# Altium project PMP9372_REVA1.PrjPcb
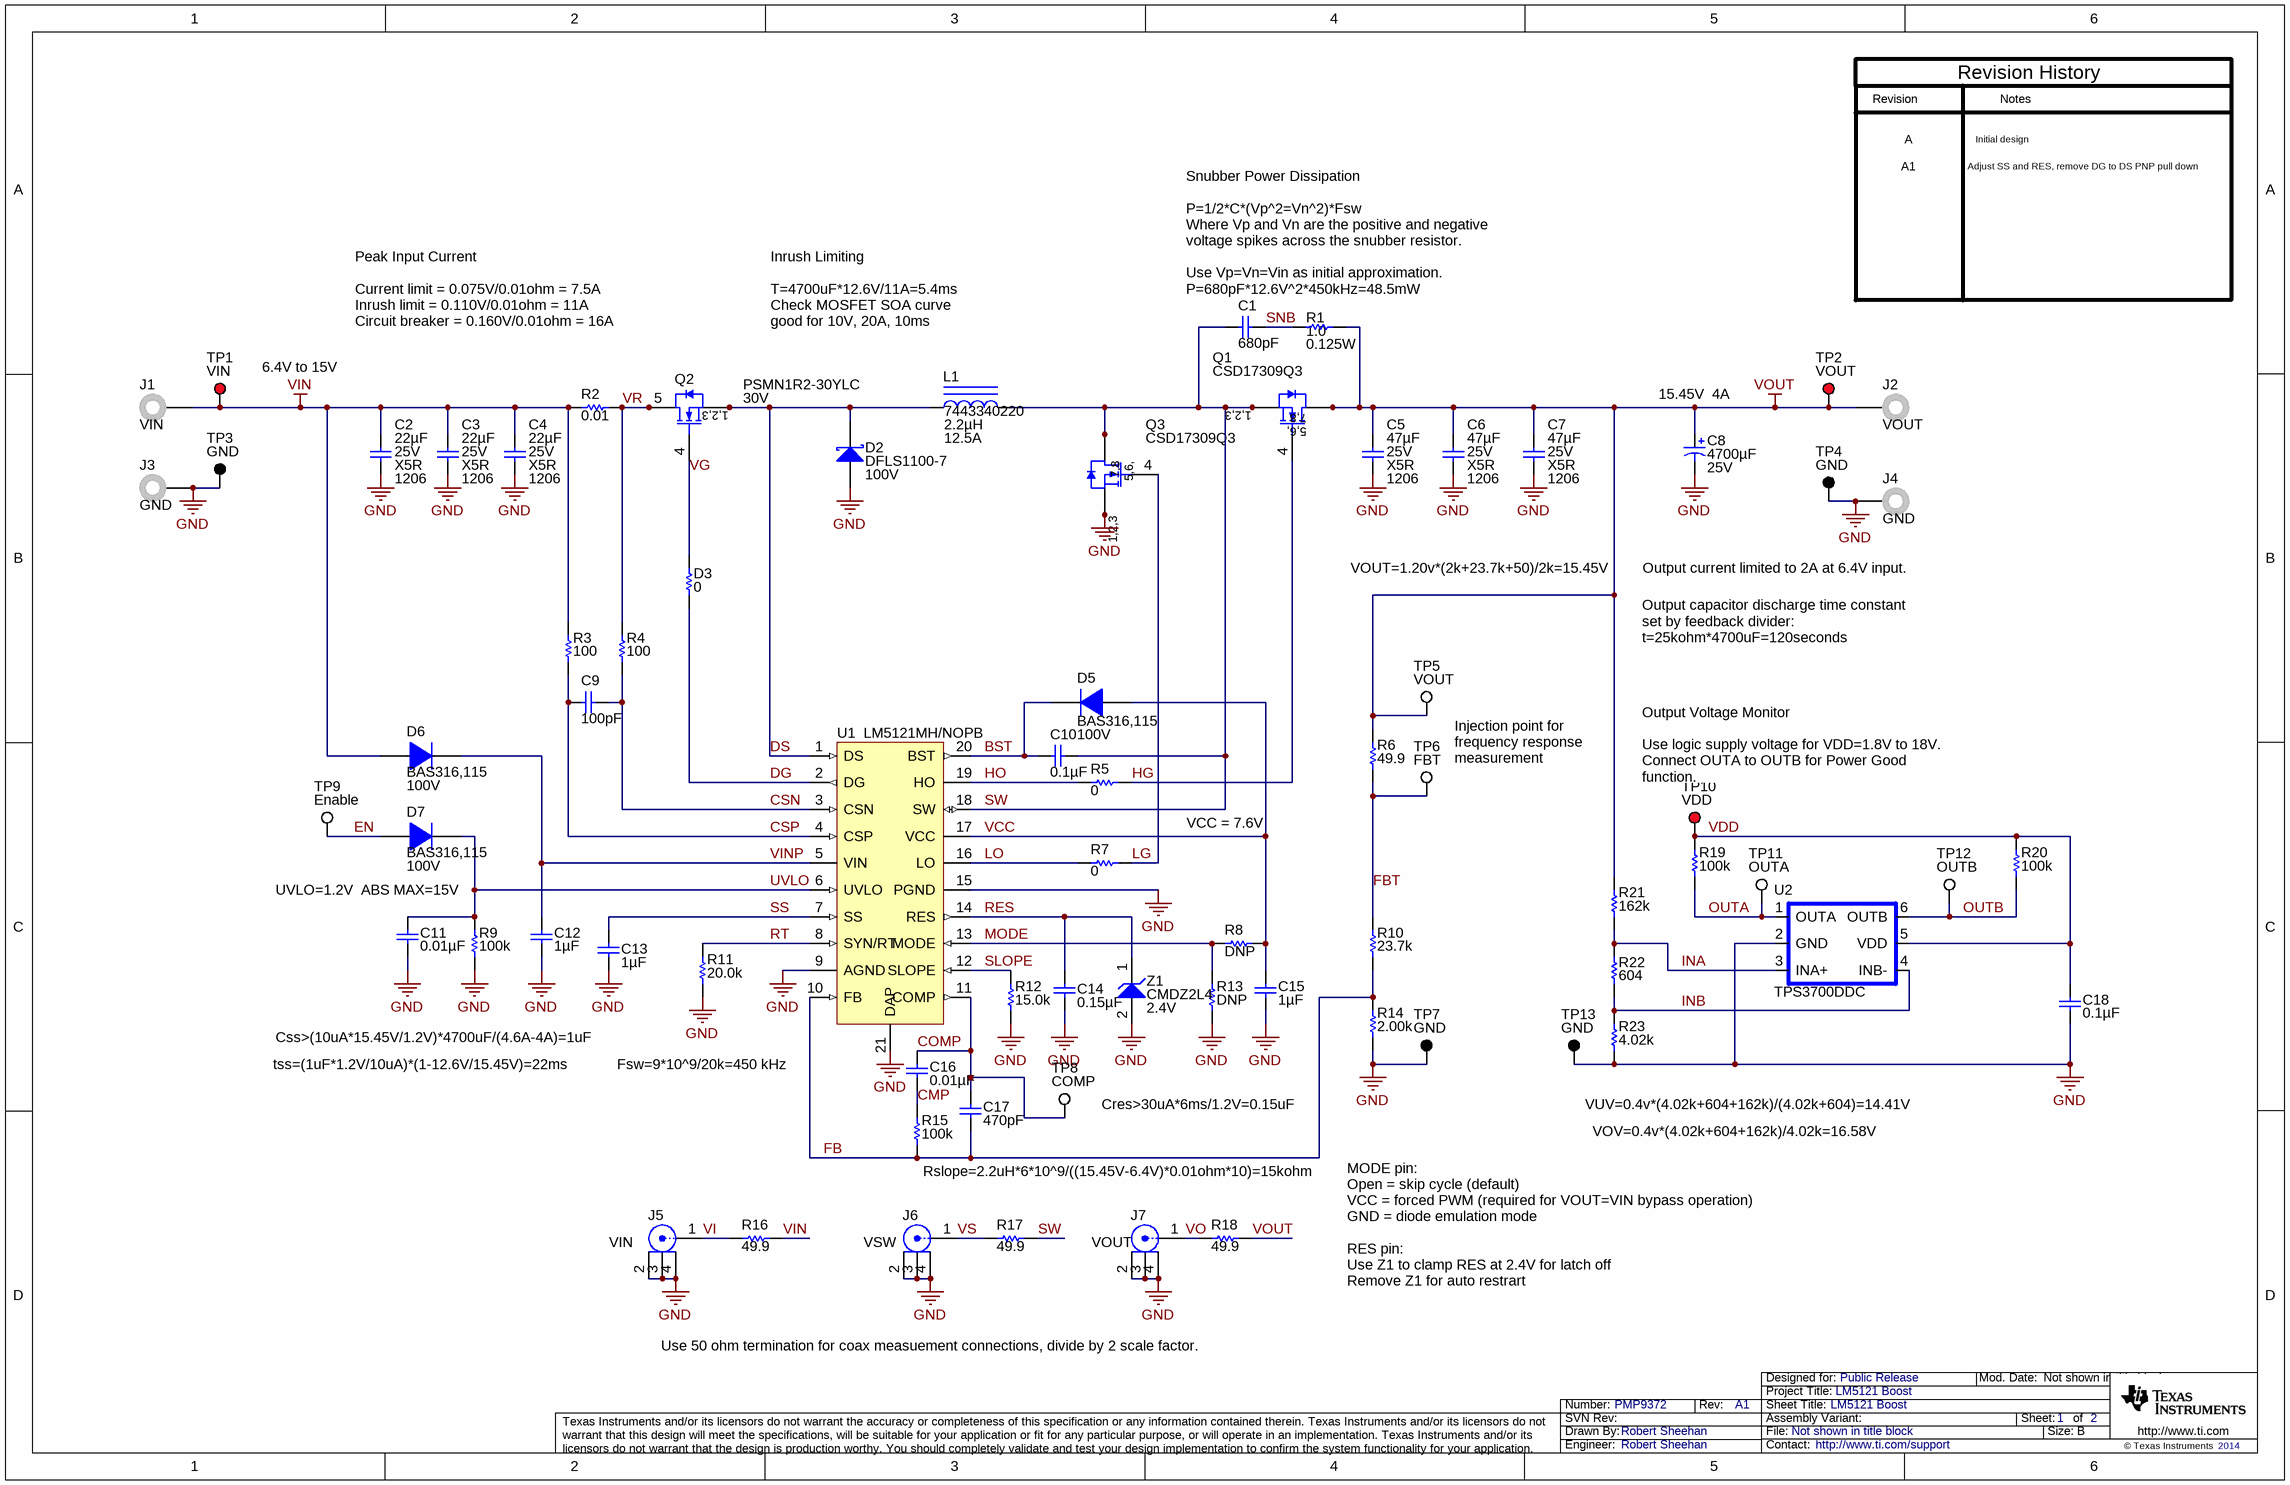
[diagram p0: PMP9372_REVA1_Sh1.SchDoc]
TechSupport: http://www.ti.com/support; SCH_Rev: A1; PRJ_Title: LM5121 Boost; PRJ_Number: PMP9372; PRJ_Engineer: Robert Sheehan; PRJ_Customer: Public Release; PCB_Rev: A; PCB_Layout: Robert Sheehan; CopyrightYear: 2014
2 sheets, 91 parts. Net scope: global (net labels, ports and power ports of the same name join across sheets).
Board file: PMP9372_REVA.PcbDoc
Sheets:
  PMP9372_REVA1_Sh1.SchDoc
  PMP9372_REVA1_Sh2.SchDoc

## Sheet PMP9372_REVA1_Sh1.SchDoc: LM5121 Boost
size 431 x 279 mm; Date: Not shown in title block; ApprovedBy: Not shown in title block; CheckedBy: Not shown in title block; Author: Not shown in title block; CompanyName: Not shown in title block; DrawnBy: Robert Sheehan; Engineer: Not shown in title block; Organization: Not shown in title block; Address1: Not shown in title block; Address2: Not shown in title block; Address3: Not shown in title block; Address4: Not shown in title block; DocumentNumber: 1; Revision: Use project parameter SCH_Rev; SheetNumber: 1; SheetTotal: 2; PageSetup: Record=PageOptions|CenterHorizontal=True|CenterVertical=True|PrintScale=1.00|XCorrection=1.00|YCorrection=1.00|PrintKind=0|BorderSize=5000000|LeftOffset=0|BottomOffset=0|Orientation=2|PaperLength=1000|PaperWidth=1000|Scale=100|PaperSource=15|PrintQuality=600|MediaType=1|DitherType=10|PaperKind=Letter|PrintScaleMode=1

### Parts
C1  ValueDisplayed: 680pF  [0603]  (hidden comment: GRM1885C1H681JA01D)
C2  TempCo: X5R  Value2: 25V  ValueDisplayed: 22µF  [1206]  (hidden comment: GRM31CR61E226KE15L)
C3  TempCo: X5R  Value2: 25V  ValueDisplayed: 22µF  [1206]  (hidden comment: GRM31CR61E226KE15L)
C4  TempCo: X5R  Value2: 25V  ValueDisplayed: 22µF  [1206]  (hidden comment: GRM31CR61E226KE15L)
C5  TempCo: X5R  Value2: 25V  ValueDisplayed: 47µF  [1206]  (hidden comment: C3216X5R1E476M160AC)
C6  TempCo: X5R  Value2: 25V  ValueDisplayed: 47µF  [1206]  (hidden comment: C3216X5R1E476M160AC)
C7  TempCo: X5R  Value2: 25V  ValueDisplayed: 47µF  [1206]  (hidden comment: C3216X5R1E476M160AC)
C8  ValueDisplayed: 4700µF  Value2: 25V  [CAPPR7.5-16X31.5H2]  (hidden comment: UKA1E472MHD)
C9  ValueDisplayed: 100pF  [0402]  (hidden comment: GRM1555C1H101JA01D)
C10  ValueDisplayed: 0.1µF  [0603_HV]  (hidden comment: GRM188R71C104KA01D)
C11  ValueDisplayed: 0.01µF  [0402]  (hidden comment: GRM155R71H103KA88D)
C12  ValueDisplayed: 1µF  [0402]  (hidden comment: C1005X5R1E105K050BC)
C13  ValueDisplayed: 1µF  [0402]  (hidden comment: C1005X5R1E105K050BC)
C14  ValueDisplayed: 0.15µF  [0402]  (hidden comment: GRM155R61A154KE19D)
C15  ValueDisplayed: 1µF  [0603_HV]  (hidden comment: GRM188R61E105KA12D)
C16  ValueDisplayed: 0.01µF  [0402]  (hidden comment: GRM155R71E103KA01D)
C17  ValueDisplayed: 470pF  [0402]  (hidden comment: C1005C0G1H471J)
C18  ValueDisplayed: 0.1µF  [0603_HV]  (hidden comment: GRM188R71C104KA01D)
D2  DFLS1100-7  value 100V  [powerDI123]
D3  value 0  [0402]  (hidden comment: CRCW04020000Z0ED)
D5  BAS316,115  value 100V  [sod-323]
D6  BAS316,115  value 100V  [sod-323]
D7  BAS316,115  value 100V  [sod-323]
J1  VIN  [Keystone575-8]
J2  VOUT  [Keystone575-8]
J3  GND  [Keystone575-8]
J4  GND  [Keystone575-8]
J5  VIN  [A-1JB]
J6  VSW  [A-1JB]
J7  VOUT  [A-1JB]
L1  7443340220  ValueDisplayed: 2.2µH  Value2: 12.5A  [WE-HCC-8X7]
Q1  CSD17309Q3  [TRANS_NexFET_Q3]
Q2  PSMN1R2-30YLC  value 30V  [LFPAK]
Q3  CSD17309Q3  [TRANS_NexFET_Q3]
R1  value 1.0  Value2: 0.125W  [0805_HV]  (hidden comment: CRCW08051R00JNEA)
R2  value 0.01  [2010M]  (hidden comment: CSRN2010FK10L0)
R3  value 100  [0402]  (hidden comment: CRCW0402100RJNED)
R4  value 100  [0402]  (hidden comment: CRCW0402100RJNED)
R5  value 0  [0402]  (hidden comment: CRCW04020000Z0ED)
R6  value 49.9  [0402]  (hidden comment: CRCW040249R9FKED)
R7  value 0  [0402]  (hidden comment: CRCW04020000Z0ED)
R8  value DNP  [0402]  (hidden comment: DNP1)
R9  value 100k  [0402]  (hidden comment: CRCW0402100KJNED)
R10  value 23.7k  [0402]  (hidden comment: CRCW040223K7FKED)
R11  value 20.0k  [0402]  (hidden comment: CRCW040220K0FKED)
R12  value 15.0k  [0402]  (hidden comment: CRCW040215K0FKED)
R13  value DNP  [0402]  (hidden comment: DNP1)
R14  value 2.00k  [0402]  (hidden comment: CRCW04022K00FKED)
R15  value 100k  [0402]  (hidden comment: CRCW0402100KFKED)
R16  value 49.9  [0603]  (hidden comment: CRCW060349R9FKEA)
R17  value 49.9  [0603]  (hidden comment: CRCW060349R9FKEA)
R18  value 49.9  [0603]  (hidden comment: CRCW060349R9FKEA)
R19  value 100k  [0402]  (hidden comment: CRCW0402100KJNED)
R20  value 100k  [0402]  (hidden comment: CRCW0402100KJNED)
R21  value 162k  [0402]  (hidden comment: CRCW0402162KFKED)
R22  value 604  [0402]  (hidden comment: CRCW0402604RFKED)
R23  value 4.02k  [0402]  (hidden comment: CRCW04024K02FKED)
TP1  VIN  [Keystone5010]
TP2  VOUT  [Keystone5010]
TP3  GND  [Keystone5011]
TP4  GND  [Keystone5011]
TP5  VOUT  [Keystone5012]
TP6  FBT  [Keystone5012]
TP7  GND  [Keystone5011]
TP8  COMP  [Keystone5012]
TP9  Enable  [Keystone5012]
TP10  VDD  [Keystone5010]
TP11  OUTA  [Keystone5012]
TP12  OUTB  [Keystone5012]
TP13  GND  [Keystone5011]
U1  LM5121MH/NOPB  [PWP0020A_N]
U2  TPS3700DDC  [SOT23-6]
Z1  CMDZ2L4  value 2.4V  [sod-323]

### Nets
GND: C2.2 C3.2 C4.2 C5.2 C6.2 C7.2 C8.2(-) C11.2 C12.2 C13.2 C14.2 C15.2 C18.1 D2.2(A) J3.1 J4.1 J5.2 J5.3 J5.4 J6.2 J6.3 J6.4 J7.2 J7.3 J7.4 Q3.1(S) Q3.2(S) Q3.3(S) R9.1 R11.1 R12.1 R13.1 R14.1 R23.1 TP3.1 TP4.1 TP7.1 TP13.1 U1.9(AGND) U1.15(PGND) U1.21(DAP) U2.2(GND) Z1.2(A)
VIN: C2.1 C3.1 C4.1 D6.2(A) J1.1 R2.1 R3.2 R16.2 TP1.1
VOUT: C5.1 C6.1 C7.1 C8.1(+) J2.1 Q1.5(D) Q1.6(D) Q1.7(D) Q1.8(D) R1.2 R6.2 R18.2 R21.2 TP2.1 TP5.1
BST: C10.1 D5.1(K) U1.20(BST)
CMP: C16.2 R15.2
COMP: C16.1 C17.2 TP8.1 U1.11(COMP)
CSN: C9.1 R4.1 U1.3(CSN)
CSP: C9.2 R3.1 U1.4(CSP)
DG: D3.2 U1.2(DG)
DS: D2.1(K) L1.1 Q2.1(S) Q2.2(S) Q2.3(S) U1.1(DS)
EN: D7.2(A) TP9.1
FB: C17.1 R10.1 R14.2 R15.1 U1.10(FB)
FBT: R6.1 R10.2 TP6.1
HG: Q1.4(G) R5.2
HO: R5.1 U1.19(HO)
INA: R21.1 R22.2 U2.3(INA+)
INB: R22.1 R23.2 U2.4(INB-)
LG: Q3.4(G) R7.2
LO: R7.1 U1.16(LO)
MODE: R8.2 R13.2 U1.13(MODE)
OUTA: R19.1 TP11.1 U2.1(OUTA)
OUTB: R20.1 TP12.1 U2.6(OUTB)
RES: C14.1 U1.14(RES) Z1.1(K)
RT: R11.2 U1.8(SYN/RT)
SLOPE: R12.2 U1.12(SLOPE)
SNB: C1.1 R1.1
SS: C13.1 U1.7(SS)
SW: C1.2 C10.2 L1.2 Q1.1(S) Q1.2(S) Q1.3(S) Q3.5(D) Q3.6(D) Q3.7(D) Q3.8(D) R17.2 U1.18(SW)
UVLO: C11.1 D7.1(K) R9.2 U1.6(UVLO)
VCC: C15.1 D5.2(A) R8.1 U1.17(VCC)
VDD: C18.2 R19.2 R20.2 TP10.1 U2.5(VDD)
VG: D3.1 Q2.4(G)
VI: J5.1 R16.1
VINP: C12.1 D6.1(K) U1.5(VIN)
VO: J7.1 R18.1
VR: Q2.5(D) Q2.6(D) R2.2 R4.2
VS: J6.1 R17.1

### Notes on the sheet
- Revision
- Notes
- Revision History
- A
- A1
- Initial design
- Adjust SS and RES, remove DG to DS PNP pull down
- Snubber Power Dissipation
  P=1/2*C*(Vp^2=Vn^2)*Fsw
  Where Vp and Vn are the positive and negative voltage spikes across the snubber resistor.
  Use Vp=Vn=Vin as initial approximation.
  P=680pF*12.6V^2*450kHz=48.5mW
- (near TP1) 6.4V to 15V
- Peak Input Current
  Current limit = 0.075V/0.01ohm = 7.5A
  Inrush limit = 0.110V/0.01ohm = 11A
  Circuit breaker = 0.160V/0.01ohm = 16A
- Inrush Limiting
  T=4700uF*12.6V/11A=5.4ms
  Check MOSFET SOA curve
  good for 10V, 20A, 10ms
- (near C8) 15.45V  4A
- VOUT=1.20v*(2k+23.7k+50)/2k=15.45V
- Output current limited to 2A at 6.4V input.
- Output capacitor discharge time constant set by feedback divider:
  t=25kohm*4700uF=120seconds
- VCC = 7.6V
- Injection point for frequency response measurement
- (near TP10) Output Voltage Monitor
  Use logic supply voltage for VDD=1.8V to 18V.
  Connect OUTA to OUTB for Power Good function.
- UVLO=1.2V  ABS MAX=15V
- Css>(10uA*15.45V/1.2V)*4700uF/(4.6A-4A)=1uF
- tss=(1uF*1.2V/10uA)*(1-12.6V/15.45V)=22ms
- Fsw=9*10^9/20k=450 kHz
- (near TP8) Cres>30uA*6ms/1.2V=0.15uF
- VUV=0.4v*(4.02k+604+162k)/(4.02k+604)=14.41V
- (near R15) Rslope=2.2uH*6*10^9/((15.45V-6.4V)*0.01ohm*10)=15kohm
- VOV=0.4v*(4.02k+604+162k)/4.02k=16.58V
- MODE pin:
  Open = skip cycle (default)
  VCC = forced PWM (required for VOUT=VIN bypass operation)
  GND = diode emulation mode
  RES pin:
  Use Z1 to clamp RES at 2.4V for latch off
  Remove Z1 for auto restrart
- Use 50 ohm termination for coax measuement connections, divide by 2 scale factor.

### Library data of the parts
C1 = GRM1885C1H681JA01D: CAP, CERM, 680pF, 50V, +/-5%, C0G/NP0, 0603; Manufacturer: MuRata; Polarized: N; CompType: Capacitor; U/M: EA; Cap_F: 0.00000000068; Tolerance_%: 5; Value1: Unknown; VDC_V: 50; TaMin_C: -55; TaMax_C: 125
C2-C4 = GRM31CR61E226KE15L: CAP, CERM, 22uF, 25V, +/-10%, X5R, 1206; Manufacturer: MuRata; Polarized: N; CompType: Capacitor; U/M: EA; Cap_F: 0.000022; Tolerance_%: 10; VDC_V: 25; TaMin_C: -55; TaMax_C: 85
C5-C7 = C3216X5R1E476M160AC: CAP, CERM, 47uF, 25V, +/-20%, X5R, 1206; Manufacturer: TDK; Polarized: N; CompType: Capacitor; U/M: EA; Cap_F: 0.000047; Tolerance_%: 20; Value1: Unknown; VDC_V: 25; TaMin_C: -55; TaMax_C: 85
C8 = UKA1E472MHD: CAP, AL, 4700uF, 25V, +/-20%, TH; Manufacturer: Nichicon; IRMS_A: 1.710; Polarized: Y; TaMax_C: 105; TaMin_C: -25; Tolerance_%: 20; VDC_V: 25; CompType: Capacitor; Cap_F: 4700E-6; U/M: EA; Dielectric: AE
C9 = GRM1555C1H101JA01D: CAP, CERM, 100pF, 50V, +/-5%, C0G/NP0, 0402; Manufacturer: MuRata; Polarized: N; CompType: Capacitor; U/M: EA; Cap_F: 0.0000000001; Tolerance_%: 5; Value1: Unknown; VDC_V: 50; TaMin_C: -55; TaMax_C: 125
C10 C18 = GRM188R71C104KA01D: CAP, CERM, 0.1uF, 16V, +/-10%, X7R, 0603; Manufacturer: MuRata; Polarized: N; CompType: Capacitor; U/M: EA; Cap_F: 0.0000001; Tolerance_%: 10; Value1: Unknown; VDC_V: 16; TaMin_C: -55; TaMax_C: 125; Cap_Case: 0603
C11 = GRM155R71H103KA88D: CAP, CERM, 0.01uF, 50V, +/-10%, X7R, 0402; Manufacturer: MuRata; Polarized: N; CompType: Capacitor; U/M: EA; Cap_F: 0.00000001; Tolerance_%: 10; Value1: Unknown; VDC_V: 50; TaMin_C: -55; TaMax_C: 125
C12 C13 = C1005X5R1E105K050BC: CAP, CERM, 1uF, 25V, +/-10%, X5R, 0402; Manufacturer: TDK; Polarized: N; CompType: Capacitor; U/M: EA; Cap_F: 0.000001; Tolerance_%: 10; Value1: Unknown; VDC_V: 25; TaMin_C: -55; TaMax_C: 80
C14 = GRM155R61A154KE19D: CAP, CERM, 0.15uF, 10V, +/-10%, X5R, 0402; Manufacturer: MuRata; Polarized: N; CompType: Capacitor; U/M: EA; Cap_F: 0.00000015; Tolerance_%: 10; Value1: Unknown; TaMin_C: -55; TaMax_C: 85
C15 = GRM188R61E105KA12D: CAP, CERM, 1uF, 25V, +/-10%, X5R, 0603; Manufacturer: MuRata; Polarized: N; CompType: Capacitor; U/M: EA; Cap_F: 0.000001; Tolerance_%: 10; Value1: Unknown; VDC_V: 25; TaMin_C: -55; TaMax_C: 85; Cap_Case: 0603
C16 = GRM155R71E103KA01D: CAP, CERM, 0.01uF, 25V, +/-10%, X7R, 0402; Manufacturer: MuRata; Polarized: N; CompType: Capacitor; U/M: EA; Cap_F: 0.00000001; Tolerance_%: 10; Value1: Unknown; VDC_V: 25; TaMin_C: -55; TaMax_C: 125
C17 = C1005C0G1H471J: CAP, CERM, 470pF, 50V, +/-5%, C0G/NP0, 0402; Manufacturer: TDK; Polarized: N; CompType: Capacitor; U/M: EA; Cap_F: 0.00000000047; Tolerance_%: 5; ESR_Ohm: 0.0788; Value1: 0.0788 ohm; VDC_V: 50; TaMin_C: -55; TaMax_C: 125
D2 = DFLS1100-7: Diode, Schottky, 100V, 1A, PowerDI123; Manufacturer: Diodes Inc.; U/M: EA; Vf_V: 0.77; Value2: 0.77V; Io_A: 1; Vr_V: 100; TJmax_C: 175; RJC_CperW: 7
D3 = CRCW04020000Z0ED: RES, 0 ohm, 5%, 0.063W, 0402; Manufacturer: Vishay-Dale; CompType: Resistor; U/M: EA; Value_Code: 0000; Tolerance_%: 5; Power_W: 0.063; VDC_V: 50; TempCo: 200 ppm/C; EIA_Code: E24
D5-D7 = BAS316,115: Diode, Ultrafast, 100V, 0.25A, SOD-323; Manufacturer: NXP Semiconductor; U/M: EA; Vf_V: 1.4; Value2: 1.4V; Io_A: 0.25; Vr_V: 100; TJmax_C: 150
J1-J4 = 575-8: Standard Banana Jack, Uninsulated, 8.9mm; Manufacturer: Keystone; CompType: Connector; U/M: EA
J5-J7 = A-1JB: Connector, RF Jack, Vertical, Gold, SMD; Manufacturer: Amphenol; SymbolCreator: crossc; U/M: EA; Value: 50 ohm
L1 = 7443340220: Inductor, Shielded Drum Core, Ferrite, 2.2uH, 12.5A, 0.0044 ohm, SMD; Manufacturer: Wurth Elektronik eiSos; Ind_H: 2.2E-6; Imax_A: 12.5; Irms: 16.5A @ 50C rise; Isat: 12.5A @ 30% inductance drop; DCR_ohm: 0.0044; U/M: EA
Q1 Q3 = CSD17309Q3: MOSFET, N-CH, 30V, 60A, SON 3.3x3.3mm; Manufacturer: Texas Instruments; Alternate Manufacturer: None; U/M: EA; ChType: N; VdsMax_V: 30; Value1: 0.0049 ohm; Rdson45_Ohm: 0.0049; Value2: 7.5 nC; QgTyp_nC: 7.5; Vgs_V: 10; IdsMax_A: 60
Q2 = PSMN1R2-30YLC: MOSFET, N-CH, 30V, 100A, LFPAK; Manufacturer: NXP Semiconductor; Alternate Manufacturer: None; U/M: EA; ChType: N; VdsMax_V: 30; Value1: 1.25 mohm @ 10V; Rdson45_Ohm: 0.00165; Value2: 78 nC @ 10V; QgTyp_nC: 50; Vgs_V: 20; IdsMax_A: 100
R1 = CRCW08051R00JNEA: RES, 1.0 ohm, 5%, 0.125W, 0805; Manufacturer: Vishay-Dale; CompType: Resistor; Res_ohm: 1; Value_Code: 1R00; Tolerance_%: 5; Power_W: 0.125; VDC_V: 150; TempCo: 200 ppm/C; EIA_Code: E24; U/M: EA
R2 = CSRN2010FK10L0: RES, 0.01 ohm, 1%, 1W, 2010; Manufacturer: Stackpole Electronics Inc; CompType: Resistor; Value_Code: R010; Tolerance_%: 1; TempCo: 250 ppm/C; EIA_Code: E96; U/M: EA
R3 R4 = CRCW0402100RJNED: RES, 100 ohm, 5%, 0.063W, 0402; Manufacturer: Vishay-Dale; CompType: Resistor; Value_Code: 100R; Tolerance_%: 5; Power_W: 0.063; VDC_V: 50; TempCo: 200 ppm/C; EIA_Code: E24; U/M: EA
R5 R7 = CRCW04020000Z0ED: RES, 0 ohm, 5%, 0.063W, 0402; Manufacturer: Vishay-Dale; CompType: Resistor; Value_Code: 0000; Tolerance_%: 5; Power_W: 0.063; VDC_V: 50; TempCo: 200 ppm/C; EIA_Code: E24; U/M: EA
R6 = CRCW040249R9FKED: RES, 49.9 ohm, 1%, 0.063W, 0402; Manufacturer: Vishay-Dale; CompType: Resistor; Value_Code: 49R9; Tolerance_%: 1; Power_W: 0.063; VDC_V: 50; TempCo: 100 ppm/C; EIA_Code: E96; U/M: EA
R8 R13 = Resistor: RES, xxx ohm, x%, xW, [PackageReference]; Manufacturer: Used in BOM report; U/M: EA
R9 R19 R20 = CRCW0402100KJNED: RES, 100k ohm, 5%, 0.063W, 0402; Manufacturer: Vishay-Dale; CompType: Resistor; Res_ohm: 100000; Tolerance_%: 5; Power_W: 0.063; VDC_V: 50; TempCo: 200 ppm/C; EIA_Code: E24; U/M: EA
R10 = CRCW040223K7FKED: RES, 23.7k ohm, 1%, 0.063W, 0402; Manufacturer: Vishay-Dale; CompType: Resistor; Res_ohm: 23700; Value_Code: 23k7; Tolerance_%: 1; Power_W: 0.063; VDC_V: 50; TempCo: 100 ppm/C; EIA_Code: E96; U/M: EA
R11 = CRCW040220K0FKED: RES, 20.0k ohm, 1%, 0.063W, 0402; Manufacturer: Vishay-Dale; CompType: Resistor; Res_ohm: 20000; Value_Code: 20k0; Tolerance_%: 1; Power_W: 0.063; VDC_V: 50; TempCo: 100 ppm/C; EIA_Code: E96; U/M: EA
R12 = CRCW040215K0FKED: RES, 15.0k ohm, 1%, 0.063W, 0402; Manufacturer: Vishay-Dale; CompType: Resistor; Res_ohm: 15000; Value_Code: 15k0; Tolerance_%: 1; Power_W: 0.063; VDC_V: 50; TempCo: 100 ppm/C; EIA_Code: E96; U/M: EA
R14 = CRCW04022K00FKED: RES, 2.00k ohm, 1%, 0.063W, 0402; Manufacturer: Vishay-Dale; CompType: Resistor; Res_ohm: 2000; Value_Code: 2k00; Tolerance_%: 1; Power_W: 0.063; VDC_V: 50; TempCo: 100 ppm/C; EIA_Code: E96; U/M: EA
R15 = CRCW0402100KFKED: RES, 100k ohm, 1%, 0.063W, 0402; Manufacturer: Vishay-Dale; CompType: Resistor; Res_ohm: 100000; Tolerance_%: 1; Power_W: 0.063; VDC_V: 50; TempCo: 100 ppm/C; EIA_Code: E96; U/M: EA
R16-R18 = CRCW060349R9FKEA: RES, 49.9 ohm, 1%, 0.1W, 0603; Manufacturer: Vishay-Dale; CompType: Resistor; Value_Code: 49R9; Tolerance_%: 1; Power_W: 0.1; VDC_V: 75; TempCo: 100 ppm/C; EIA_Code: E96; U/M: EA
R21 = CRCW0402162KFKED: RES, 162k ohm, 1%, 0.063W, 0402; Manufacturer: Vishay-Dale; CompType: Resistor; Res_ohm: 162000; Tolerance_%: 1; Power_W: 0.063; VDC_V: 50; TempCo: 100 ppm/C; EIA_Code: E96; U/M: EA
R22 = CRCW0402604RFKED: RES, 604 ohm, 1%, 0.063W, 0402; Manufacturer: Vishay-Dale; CompType: Resistor; Value_Code: 604R; Tolerance_%: 1; Power_W: 0.063; VDC_V: 50; TempCo: 100 ppm/C; EIA_Code: E96; U/M: EA
R23 = CRCW04024K02FKED: RES, 4.02k ohm, 1%, 0.063W, 0402; Manufacturer: Vishay-Dale; CompType: Resistor; Res_ohm: 4020; Value_Code: 4k02; Tolerance_%: 1; Power_W: 0.063; VDC_V: 50; TempCo: 100 ppm/C; EIA_Code: E96; U/M: EA
TP1 TP2 TP10 = 5010: Test Point, Multipurpose, Red, TH; Manufacturer: Keystone; CompType: Test Point Loop; U/M: EA
TP3 TP4 TP7 TP13 = 5011: Test Point, Multipurpose, Black, TH; Manufacturer: Keystone; CompType: Test Point Loop; U/M: EA
TP5 TP6 TP8 TP9 TP11 TP12 = 5012: Test Point, Multipurpose, White, TH; Manufacturer: Keystone; CompType: Test Point Loop; U/M: EA
U1 = LM5121MH/NOPB: Wide Input Synchronous Boost Controller with Disconnection Switch Control, PWP0020A; Alternate Manufacturer: None; Manufacturer: Texas Instruments; SymbolCreator: a0411947; CompType: IC; U/M: EA
U2 = TPS3700DDC: IC,  High Voltage, Over-Under Voltage Supervisory; Manufacturer: TI; Alternate Manufacturer: None; Area: 23200
Z1 = MMSZ5242BS-7-F: Diode, Zener, 2.4V, Sharp Knee, SOD-323; Manufacturer: Diodes Inc.; Alternate Manufacturer: Fairchild Semiconductor; Alternate PartNumber: MM3Z2V4B; U/M: EA; Vz_V: 2.4; RJA_CperW: 350

## Sheet PMP9372_REVA1_Sh2.SchDoc: Hardware
size 431 x 279 mm; Date: Not shown in title block; ApprovedBy: Not shown in title block; CheckedBy: Not shown in title block; Author: Not shown in title block; CompanyName: Not shown in title block; DrawnBy: Robert Sheehan; Engineer: Not shown in title block; Organization: Not shown in title block; Address1: Not shown in title block; Address2: Not shown in title block; Address3: Not shown in title block; Address4: Not shown in title block; DocumentNumber: 2; Revision: Use project parameter SCH_Rev; SheetNumber: 2; SheetTotal: 2; PageSetup: Record=PageOptions|CenterHorizontal=True|CenterVertical=True|PrintScale=1.00|XCorrection=1.00|YCorrection=1.00|PrintKind=0|BorderSize=5000000|LeftOffset=0|BottomOffset=0|Orientation=2|PaperLength=1000|PaperWidth=1000|Scale=100|PaperSource=15|PrintQuality=600|MediaType=1|DitherType=10|PaperKind=Letter|PrintScaleMode=1
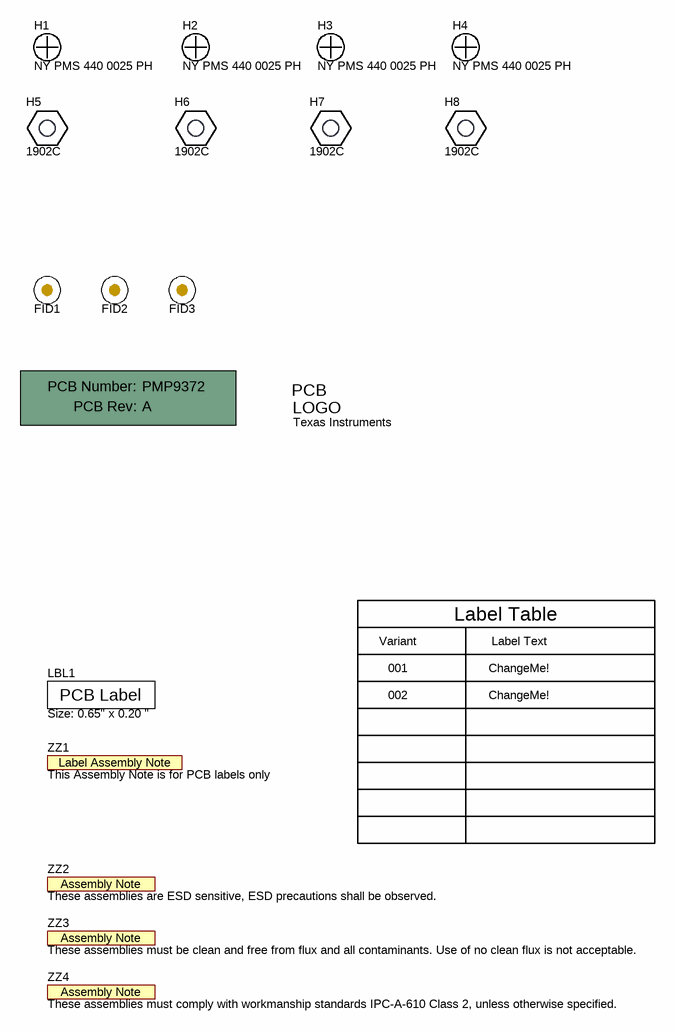
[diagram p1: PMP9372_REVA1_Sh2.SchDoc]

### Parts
!PCB1  Printed Circuit Board  (value not drawn)  (mechanical)
FID1  Fiducial  [Fiducial10-20]  (value not drawn)
FID2  Fiducial  [Fiducial10-20]  (value not drawn)
FID3  Fiducial  [Fiducial10-20]  (value not drawn)
H1  NY PMS 440 0025 PH  [NY PMS 440 0025 PH]
H2  NY PMS 440 0025 PH  [NY PMS 440 0025 PH]
H3  NY PMS 440 0025 PH  [NY PMS 440 0025 PH]
H4  NY PMS 440 0025 PH  [NY PMS 440 0025 PH]
H5  1902C  [Keystone_1902C]
H6  1902C  [Keystone_1902C]
H7  1902C  [Keystone_1902C]
H8  1902C  [Keystone_1902C]
LBL1  Size: 0.65" x 0.20 "  [Label_650x200]
Logo1  Texas Instruments  [TI_Stacked_SolderMask_Small]  (no BOM)
ZZ1  This Assembly Note is for PCB labels only  [AssemblyNoteLabel]  (no BOM)
ZZ2  These assemblies are ESD sensitive, ESD precautions shall be observed.  [AssemblyNote]  (no BOM)
ZZ3  These assemblies must be clean and free from flux and all contaminants. Use of no clean flux is not acceptable.  [AssemblyNote]  (no BOM)
ZZ4  These assemblies must comply with workmanship standards IPC-A-610 Class 2, unless otherwise specified.  [AssemblyNote]  (no BOM)

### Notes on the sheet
- Variant
- Label Table
- Label Text
- 001
- 002
- ChangeMe!

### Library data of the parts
!PCB1 = PCB: Manufacturer: Any; PartNumber: PMP9372; SymbolCreator: a0412235
FID1-FID3 = Fiducial: Fiducial mark.  There is nothing to buy or mount.; SymbolCreator: codlsc
H1-H4 = NY PMS 440 0025 PH: Machine Screw, Round, #4-40 x 1/4, Nylon, Philips panhead; Manufacturer: B&F Fastener Supply; CompType: Hardware; SymbolCreator: codlsc; U/M: EA
H5-H8 = 1902C: Standoff, Hex, 0.5"L #4-40 Nylon; Manufacturer: Keystone; CompType: Hardware
LBL1 = THT-14-423-10: Thermal Transfer Printable Labels, 0.650" W x 0.200" H - 10,000 per roll; Manufacturer: Brady; SymbolCreator: a0412235; CompType: Label
Logo1 = TI_Logo: Texas Instrument Corporate Signature; SymbolCreator: codlsc
ZZ1 = AssemblyNoteLabel: SymbolCreator: a0412235
ZZ2-ZZ4 = AssemblyNote: SymbolCreator: codlsc

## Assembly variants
001: not fitted FID1 FID2 FID3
